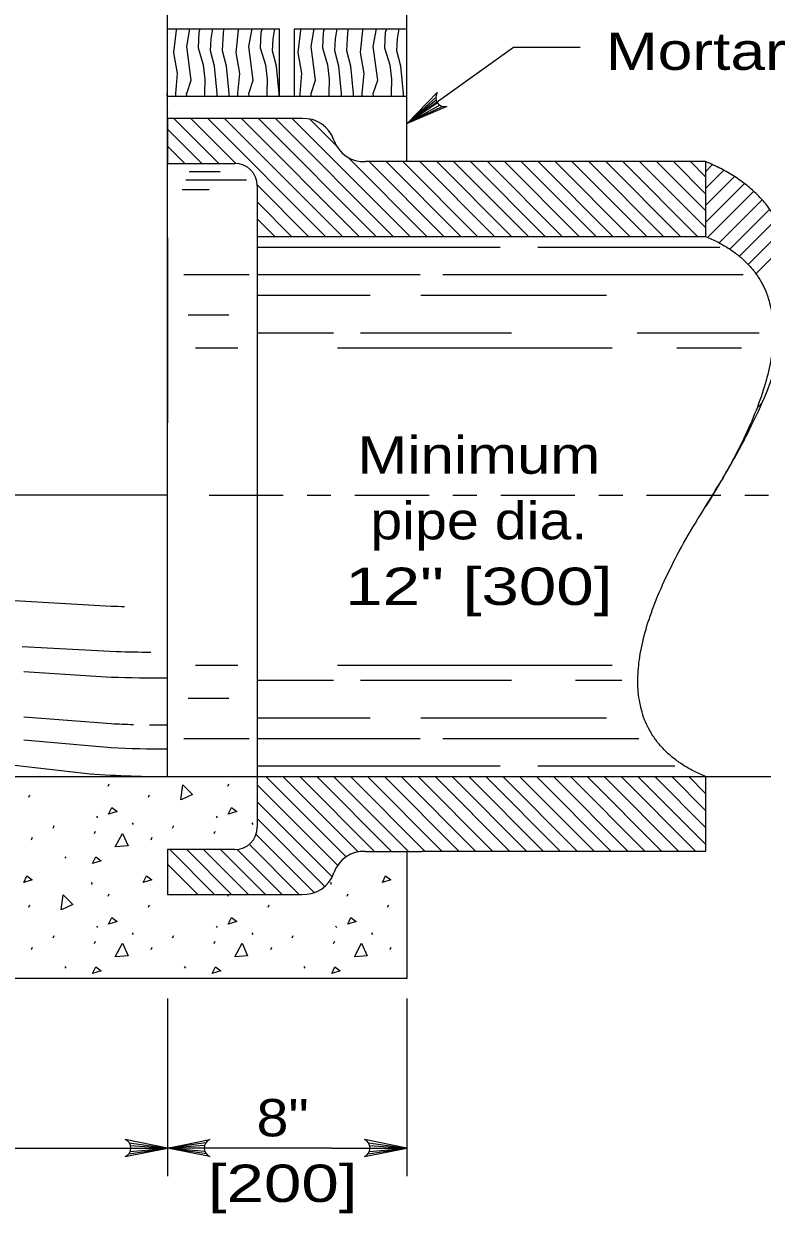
# Model space of a CAD drawing. Extents: x 1083.1 to 1117.1, y 719.4 to 763.4.
# Drawn here: x 1108.681 to 1111.769, y 727.812 to 732.781 of the extents above; entities that cross this region are included whole.
import ezdxf
from ezdxf.enums import TextEntityAlignment as Align

# ---------------------------------------------------------------- set-up
doc = ezdxf.new("R2010")
doc.units = 0
doc.header["$LTSCALE"] = 0.062
doc.linetypes.add('DOT_DASHED', pattern=[7.7, 5, -1.2, 0.3, -1.2])
doc.layers.add('1', color=7, linetype='Continuous', lineweight=13)

msp = doc.modelspace()

# ---------------------------------------------------------------- linework, layer by layer
at = {"layer": '1', "lineweight": 25}
for p, q in [((1109.28242, 729.63575), (1109.28242, 733.88517)), ((1109.84492, 732.38542), (1109.28242, 732.38542)), ((1109.28242, 732.198), (1109.56367, 732.198)), ((1111.53233, 732.20567), (1111.53233, 731.89317)), ((1109.65742, 731.89308), (1109.65742, 729.63575)), ((1108.64175, 729.68367), (1108.9355, 729.64958)), ((1110.1105, 729.32333), (1110.34492, 729.32333)), ((1110.28242, 729.32333), (1110.28242, 728.79217)), ((1111.53233, 729.32333), (1110.34492, 729.32333)), ((1110.28242, 728.79217), (1106.03258, 728.79217))]:
    msp.add_line(p, q, dxfattribs=at)
at = {"layer": '1'}
for p, q in [((1109.28242, 732.76033), (1109.75117, 732.76033)), ((1109.75117, 732.47908), (1109.75117, 732.76033)), ((1109.28017, 732.47908), (1109.28017, 732.48983)), ((1109.28242, 732.47908), (1110.28242, 732.47908)), ((1109.31683, 732.47908), (1109.31658, 732.48983)), ((1109.36308, 732.47908), (1109.36233, 732.49075)), ((1109.437, 732.48983), (1109.4375, 732.47908)), ((1109.4895, 732.47908), (1109.4895, 732.48983)), ((1109.54017, 732.47908), (1109.54017, 732.48983)), ((1109.57683, 732.47908), (1109.57658, 732.48983)), ((1109.62308, 732.47908), (1109.62233, 732.49075)), ((1109.697, 732.48983), (1109.6975, 732.47908)), ((1109.7495, 732.47908), (1109.7495, 732.48983)), ((1109.83683, 732.47908), (1109.83658, 732.48983)), ((1109.88308, 732.47908), (1109.88233, 732.49075)), ((1109.957, 732.48983), (1109.9575, 732.47908)), ((1110.0095, 732.47908), (1110.0095, 732.48983)), ((1110.06017, 732.47908), (1110.06017, 732.48983)), ((1110.09683, 732.47908), (1110.09658, 732.48983)), ((1110.14308, 732.47908), (1110.14233, 732.49075)), ((1110.217, 732.48983), (1110.2175, 732.47908)), ((1110.2695, 732.47908), (1110.2695, 732.48983)), ((1110.404, 732.474), (1110.285, 732.36425)), ((1110.40583, 732.46175), (1110.285, 732.36425)), ((1110.411, 732.4515), (1110.285, 732.36425)), ((1109.28242, 732.41658), (1109.28008, 732.41658)), ((1109.28117, 732.41658), (1109.28242, 732.41233)), ((1110.4215, 732.44125), (1110.285, 732.36425)), ((1110.43242, 732.43625), (1110.285, 732.36425)), ((1109.28242, 732.38542), (1109.28242, 732.198)), ((1109.4965, 732.198), (1109.309, 732.38542)), ((1109.56767, 732.19758), (1109.37975, 732.38542)), ((1109.94275, 731.89317), (1109.45042, 732.38542)), ((1110.0135, 731.89317), (1109.52117, 732.38542)), ((1110.08417, 731.89317), (1109.59183, 732.38542)), ((1110.15492, 731.89317), (1109.66258, 732.38542)), ((1110.22558, 731.89317), (1109.73325, 732.38542)), ((1110.29633, 731.89317), (1109.804, 732.38542)), ((1109.98942, 732.27075), (1109.87692, 732.38317)), ((1109.42583, 732.198), (1109.28242, 732.34142)), ((1109.35508, 732.198), (1109.28242, 732.27067)), ((1109.28442, 732.198), (1109.28242, 732.2)), ((1110.367, 731.89317), (1110.036, 732.22417)), ((1110.43775, 731.89317), (1110.12525, 732.20567)), ((1110.50842, 731.89317), (1110.19592, 732.20567)), ((1110.57917, 731.89317), (1110.26667, 732.20567)), ((1110.64983, 731.89317), (1110.33733, 732.20567)), ((1110.7205, 731.89317), (1110.40808, 732.20567)), ((1110.79117, 731.89317), (1110.47875, 732.20567)), ((1110.86192, 731.89317), (1110.5495, 732.20567)), ((1110.93267, 731.89317), (1110.62025, 732.20567)), ((1111.00333, 731.89317), (1110.69083, 732.20567)), ((1111.07408, 731.89317), (1110.76158, 732.20567)), ((1111.14475, 731.89317), (1110.83225, 732.20567)), ((1111.2155, 731.89317), (1110.903, 732.20567)), ((1111.28617, 731.89317), (1110.97367, 732.20567)), ((1111.35692, 731.89317), (1111.04442, 732.20567)), ((1111.42758, 731.89317), (1111.11508, 732.20567)), ((1111.49833, 731.89317), (1111.18583, 732.20567)), ((1111.53233, 731.92983), (1111.2565, 732.20567)), ((1111.53233, 732.00058), (1111.32725, 732.20567)), ((1111.53233, 732.07125), (1111.39792, 732.20567)), ((1111.53233, 732.142), (1111.46867, 732.20567)), ((1109.37342, 732.16392), (1109.50308, 732.16392)), ((1111.53233, 732.16325), (1111.56183, 732.19275)), ((1111.53233, 732.09258), (1111.609, 732.16925)), ((1109.28242, 732.13542), (1109.28008, 732.13542)), ((1109.35867, 732.129), (1109.61258, 732.129)), ((1109.87208, 731.89317), (1109.65717, 732.108)), ((1111.53233, 732.02183), (1111.65342, 732.14292)), ((1111.53233, 731.95117), (1111.695, 732.11383)), ((1109.34367, 732.08908), (1109.45575, 732.08908)), ((1111.54133, 731.88942), (1111.73358, 732.08167)), ((1111.589, 731.86642), (1111.76875, 732.04617)), ((1109.80133, 731.89317), (1109.65742, 732.03708)), ((1111.63333, 731.84), (1111.80042, 732.00708)), ((1109.73067, 731.89317), (1109.65742, 731.96642)), ((1111.674, 731.80992), (1111.82817, 731.96408)), ((1111.71058, 731.77592), (1111.85158, 731.91683)), ((1109.28242, 731.88658), (1109.28242, 731.1145)), ((1109.65742, 731.84867), (1110.67333, 731.84867)), ((1110.8305, 731.84867), (1111.59208, 731.84867)), ((1111.74258, 731.73725), (1111.8705, 731.865)), ((1109.28242, 731.73033), (1109.28008, 731.73033)), ((1109.35117, 731.73367), (1109.62408, 731.73367)), ((1109.65742, 731.73367), (1110.33842, 731.73367)), ((1110.43408, 731.73367), (1111.68992, 731.73367)), ((1109.65742, 731.64742), (1110.12992, 731.64742)), ((1110.34183, 731.64742), (1111.11758, 731.64742)), ((1109.36825, 731.56592), (1109.53867, 731.56592)), ((1109.28242, 731.14683), (1109.28242, 731.46583)), ((1109.65742, 731.49058), (1109.97617, 731.49058)), ((1110.08892, 731.49058), (1110.72108, 731.49058)), ((1111.24667, 731.49058), (1111.75592, 731.49058)), ((1109.28242, 731.44917), (1109.28008, 731.44917)), ((1109.399, 731.42692), (1109.57625, 731.42692)), ((1109.99325, 731.42692), (1111.1415, 731.42692)), ((1111.4115, 731.42692), (1111.68308, 731.42692)), ((1111.74742, 731.1765), (1111.76867, 731.19767)), ((1111.69367, 731.052), (1111.70417, 731.0625)), ((1109.28242, 731.04725), (1109.28008, 731.04725)), ((1111.61608, 730.90367), (1111.61858, 730.90617)), ((1109.28242, 730.85983), (1109.28008, 730.85983)), ((1108.28208, 730.39208), (1109.04675, 730.348)), ((1108.67475, 730.17933), (1109.06892, 730.15858)), ((1108.68117, 730.07492), (1109.04675, 730.052)), ((1109.399, 730.10208), (1109.57625, 730.10208)), ((1109.99325, 730.10208), (1111.1415, 730.10208)), ((1109.65742, 730.03842), (1109.97617, 730.03842)), ((1110.08892, 730.03842), (1110.72108, 730.03842)), ((1110.98767, 730.03842), (1111.18175, 730.03842)), ((1109.36825, 729.96308), (1109.53867, 729.96308)), ((1108.68117, 729.88608), (1109.04675, 729.85708)), ((1109.65742, 729.88158), (1110.12992, 729.88158)), ((1110.34183, 729.88158), (1111.11758, 729.88158)), ((1108.68117, 729.78925), (1109.04675, 729.75717)), ((1109.35117, 729.79533), (1109.62408, 729.79533)), ((1109.65742, 729.79533), (1110.33842, 729.79533)), ((1110.43408, 729.79533), (1111.25267, 729.79533)), ((1109.65742, 729.68025), (1110.67333, 729.68025)), ((1110.8305, 729.68025), (1111.40433, 729.68025)), ((1108.96517, 729.64942), (1108.96583, 729.64408)), ((1110.02925, 729.30067), (1109.69408, 729.63575)), ((1110.07958, 729.321), (1109.76475, 729.63575)), ((1110.148, 729.32333), (1109.8355, 729.63575)), ((1110.21867, 729.32333), (1109.90617, 729.63575)), ((1110.28942, 729.32333), (1109.97692, 729.63575)), ((1110.36008, 729.32333), (1110.04758, 729.63575)), ((1110.43083, 729.32333), (1110.11833, 729.63575)), ((1110.50158, 729.32333), (1110.18908, 729.63575)), ((1110.57225, 729.32333), (1110.25975, 729.63575)), ((1110.643, 729.32333), (1110.3305, 729.63575)), ((1110.71367, 729.32333), (1110.40117, 729.63575)), ((1110.78433, 729.32333), (1110.47192, 729.63575)), ((1110.855, 729.32333), (1110.54258, 729.63575)), ((1110.92575, 729.32333), (1110.61333, 729.63575)), ((1110.99642, 729.32333), (1110.684, 729.63575)), ((1111.06717, 729.32333), (1110.75467, 729.63575)), ((1111.13783, 729.32333), (1110.82533, 729.63575)), ((1111.20858, 729.32333), (1110.89608, 729.63575)), ((1111.27925, 729.32333), (1110.96675, 729.63575)), ((1111.35, 729.32333), (1111.0375, 729.63575)), ((1111.42067, 729.32333), (1111.10817, 729.63575)), ((1111.49142, 729.32333), (1111.17892, 729.63575)), ((1111.53233, 729.35308), (1111.24958, 729.63575)), ((1111.53233, 729.42383), (1111.32033, 729.63575)), ((1111.53233, 729.49458), (1111.39108, 729.63575)), ((1111.53233, 729.56525), (1111.46175, 729.63575)), ((1111.53233, 729.63575), (1112.9445, 729.63575)), ((1109.03392, 729.59525), (1109.03833, 729.60525)), ((1109.53392, 729.59525), (1109.53833, 729.60525)), ((1109.99367, 729.2655), (1109.65742, 729.60175)), ((1108.70267, 729.54967), (1108.70717, 729.55967)), ((1109.20258, 729.54967), (1109.20708, 729.55967)), ((1109.97083, 729.21767), (1109.65742, 729.53108)), ((1108.98517, 729.47092), (1108.98967, 729.46425)), ((1109.48517, 729.47092), (1109.48967, 729.46425)), ((1108.80375, 729.42092), (1108.80817, 729.43092)), ((1109.13475, 729.44267), (1109.13917, 729.436)), ((1109.30367, 729.42092), (1109.30808, 729.43092)), ((1109.63475, 729.44267), (1109.63917, 729.436)), ((1109.94067, 729.17717), (1109.65742, 729.46033)), ((1108.71383, 729.37225), (1108.71825, 729.38225)), ((1108.97683, 729.39775), (1108.98125, 729.40775)), ((1109.21375, 729.37225), (1109.21817, 729.38225)), ((1109.47683, 729.39775), (1109.48125, 729.40775)), ((1109.896, 729.15108), (1109.65242, 729.39467)), ((1109.47933, 729.1435), (1109.29183, 729.331)), ((1109.55, 729.1435), (1109.3625, 729.331)), ((1109.62075, 729.1435), (1109.43325, 729.331)), ((1109.69142, 729.1435), (1109.50392, 729.331)), ((1109.76217, 729.1435), (1109.57358, 729.332)), ((1109.83283, 729.1435), (1109.62333, 729.353)), ((1108.85258, 729.30117), (1108.857, 729.2945)), ((1109.40858, 729.1435), (1109.28242, 729.26967)), ((1108.96467, 729.19475), (1108.96583, 729.18475)), ((1109.96467, 729.19475), (1109.96583, 729.18475)), ((1109.03392, 729.13583), (1109.03833, 729.14583)), ((1109.53392, 729.13583), (1109.53733, 729.1435)), ((1110.03392, 729.13583), (1110.03833, 729.14583)), ((1108.70267, 729.09025), (1108.70717, 729.10025)), ((1109.20258, 729.09025), (1109.20708, 729.10025)), ((1109.70258, 729.09025), (1109.70708, 729.10025)), ((1110.20258, 729.09025), (1110.20708, 729.10025)), ((1108.80375, 728.96158), (1108.80817, 728.97158)), ((1108.98517, 729.01158), (1108.98967, 729.00492)), ((1109.13475, 728.98333), (1109.13917, 728.97667)), ((1109.30367, 728.96158), (1109.30808, 728.97158)), ((1109.48517, 729.01158), (1109.48967, 729.00492)), ((1109.63475, 728.98333), (1109.63917, 728.97667)), ((1109.80367, 728.96158), (1109.80808, 728.97158)), ((1109.98517, 729.01158), (1109.98967, 729.00492)), ((1110.13475, 728.98333), (1110.13917, 728.97667)), ((1108.71383, 728.91292), (1108.71825, 728.92292)), ((1108.97683, 728.93842), (1108.98125, 728.94842)), ((1109.21375, 728.91292), (1109.21817, 728.92292)), ((1109.47683, 728.93842), (1109.48125, 728.94842)), ((1109.71375, 728.91292), (1109.71817, 728.92292)), ((1109.97683, 728.93842), (1109.98125, 728.94842)), ((1110.21375, 728.91292), (1110.21817, 728.92292)), ((1108.85258, 728.84183), (1108.857, 728.83517)), ((1109.3525, 728.84183), (1109.35692, 728.83517)), ((1109.8525, 728.84183), (1109.85692, 728.83517)), ((1109.28242, 728.70883), (1109.28242, 727.96692)), ((1110.28242, 728.70883), (1110.28242, 727.96692)), ((1108.47742, 728.08383), (1109.28242, 728.08383)), ((1109.12025, 728.05908), (1109.28242, 728.08383)), ((1109.12217, 728.10633), (1109.28242, 728.08383)), ((1109.12642, 728.0695), (1109.28242, 728.08383)), ((1109.12758, 728.09517), (1109.28242, 728.08383)), ((1109.12925, 728.08383), (1109.28242, 728.08383)), ((1109.44275, 728.10633), (1109.28242, 728.08383)), ((1109.43733, 728.09517), (1109.28242, 728.08383)), ((1109.96825, 728.08383), (1109.28242, 728.08383)), ((1109.43567, 728.08383), (1109.28242, 728.08383)), ((1109.4385, 728.0695), (1109.28242, 728.08383)), ((1109.44467, 728.05908), (1109.28242, 728.08383)), ((1109.96825, 728.08383), (1110.28242, 728.08383)), ((1110.12017, 728.05908), (1110.28242, 728.08383)), ((1110.12208, 728.10633), (1110.28242, 728.08383)), ((1110.12633, 728.0695), (1110.28242, 728.08383)), ((1110.1275, 728.09517), (1110.28242, 728.08383)), ((1110.12917, 728.08383), (1110.28242, 728.08383))]:
    msp.add_line(p, q, dxfattribs=at)
at = {"layer": '1', "linetype": 'DOT_DASHED'}
msp.add_line((1109.45583, 730.81133), (1112.25767, 730.81133), dxfattribs=at)
at = {"layer": '1', "lineweight": 25}
for points in [[(1110.28242, 732.20567), (1110.28242, 733.23258), (1110.28242, 733.72892)], [(1111.53233, 732.20567), (1110.34492, 732.20567), (1110.1105, 732.20567)], [(1109.65742, 732.10425), (1109.65742, 731.89317), (1111.53233, 731.89317)], [(1109.28242, 730.81133), (1108.936, 730.81133), (1107.03175, 730.81133)], [(1106.03258, 729.63575), (1109.65742, 729.63575), (1109.65742, 729.42475)], [(1109.65742, 729.63575), (1111.53233, 729.63575), (1111.53233, 729.32333)], [(1109.56367, 729.331), (1109.28242, 729.331), (1109.28242, 729.1435), (1109.84492, 729.1435)]]:
    msp.add_lwpolyline(points, dxfattribs=at)
at = {"layer": '1'}
for points in [[(1109.31658, 732.49075), (1109.32458, 732.57308), (1109.30867, 732.66108), (1109.3195, 732.75433), (1109.32108, 732.76033)], [(1109.36242, 732.49075), (1109.38108, 732.54558), (1109.36267, 732.68692), (1109.37583, 732.76033)], [(1109.41767, 732.76033), (1109.41267, 732.74475), (1109.41033, 732.68108), (1109.43133, 732.60992), (1109.4385, 732.54958), (1109.437, 732.49075)], [(1109.4895, 732.49075), (1109.47842, 732.60458), (1109.46183, 732.669), (1109.46458, 732.71875), (1109.47125, 732.76033)], [(1109.54017, 732.49075), (1109.52908, 732.60458), (1109.5125, 732.669), (1109.51533, 732.71875), (1109.51792, 732.76033)], [(1109.57658, 732.49075), (1109.58458, 732.57308), (1109.56867, 732.66108), (1109.5795, 732.75433), (1109.58108, 732.76033)], [(1109.62242, 732.49075), (1109.64108, 732.54558), (1109.62267, 732.68692), (1109.63583, 732.76033)], [(1109.67767, 732.76033), (1109.67267, 732.74475), (1109.67033, 732.68108), (1109.69133, 732.60992), (1109.6985, 732.54958), (1109.697, 732.49075)], [(1109.7495, 732.49075), (1109.73842, 732.60458), (1109.72183, 732.669), (1109.72458, 732.71875), (1109.73125, 732.76033)], [(1109.81367, 732.47908), (1109.81367, 732.76033), (1110.28242, 732.76033)], [(1109.83658, 732.49075), (1109.84458, 732.57308), (1109.82867, 732.66108), (1109.8395, 732.75433), (1109.84108, 732.76033)], [(1109.88242, 732.49075), (1109.90108, 732.54558), (1109.88267, 732.68692), (1109.89583, 732.76033)], [(1109.93767, 732.76033), (1109.93267, 732.74475), (1109.93033, 732.68108), (1109.95133, 732.60992), (1109.9585, 732.54958), (1109.957, 732.49075)], [(1110.0095, 732.49075), (1109.99842, 732.60458), (1109.98183, 732.669), (1109.98458, 732.71875), (1109.99125, 732.76033)], [(1110.06017, 732.49075), (1110.04908, 732.60458), (1110.0325, 732.669), (1110.03533, 732.71875), (1110.03792, 732.76033)], [(1110.09658, 732.49075), (1110.10458, 732.57308), (1110.08867, 732.66108), (1110.0995, 732.75433), (1110.10108, 732.76033)], [(1110.14242, 732.49075), (1110.16108, 732.54558), (1110.14267, 732.68692), (1110.15583, 732.76033)], [(1110.19767, 732.76033), (1110.19267, 732.74475), (1110.19033, 732.68108), (1110.21133, 732.60992), (1110.2185, 732.54958), (1110.217, 732.49075)], [(1110.2695, 732.49075), (1110.25842, 732.60458), (1110.24183, 732.669), (1110.24458, 732.71875), (1110.25125, 732.76033)], [(1110.28242, 732.36492), (1110.72875, 732.68392), (1111.00842, 732.68392)], [(1110.45075, 732.43592), (1110.285, 732.36425), (1110.41042, 732.49417)], [(1109.33767, 729.53825), (1109.3465, 729.60167), (1109.38625, 729.56058), (1109.33867, 729.53858)], [(1109.06383, 729.34225), (1109.09383, 729.39883), (1109.11717, 729.34675), (1109.065, 729.34225)], [(1108.83775, 729.07883), (1108.84658, 729.14225), (1108.88633, 729.10117), (1108.83875, 729.07917)], [(1109.06383, 728.88292), (1109.09383, 728.9395), (1109.11717, 728.88742), (1109.065, 728.88292)], [(1109.56383, 728.88292), (1109.59383, 728.9395), (1109.61717, 728.88742), (1109.565, 728.88292)], [(1110.06383, 728.88292), (1110.09383, 728.9395), (1110.11717, 728.88742), (1110.065, 728.88292)], [(1109.10533, 728.04842), (1109.28242, 728.08383), (1109.10533, 728.11925)], [(1109.4595, 728.04842), (1109.28242, 728.08383), (1109.4595, 728.11925)], [(1110.10533, 728.04842), (1110.28242, 728.08383), (1110.10533, 728.11925)]]:
    msp.add_lwpolyline(points, dxfattribs=at)
for points in [[(1109.03608, 729.47867), (1109.04942, 729.50642), (1109.07167, 729.48975)], [(1109.53608, 729.47867), (1109.54942, 729.50642), (1109.57167, 729.48975)], [(1108.969, 729.27233), (1108.98233, 729.30008), (1109.00458, 729.28342)], [(1108.68075, 729.193), (1108.69408, 729.22075), (1108.71625, 729.20408)], [(1109.18067, 729.193), (1109.194, 729.22075), (1109.21617, 729.20408)], [(1110.18067, 729.193), (1110.194, 729.22075), (1110.21617, 729.20408)], [(1109.03608, 729.01933), (1109.04942, 729.04708), (1109.07167, 729.03042)], [(1109.53608, 729.01933), (1109.54942, 729.04708), (1109.57167, 729.03042)], [(1110.03608, 729.01933), (1110.04942, 729.04708), (1110.07167, 729.03042)], [(1108.969, 728.813), (1108.98233, 728.84075), (1109.00458, 728.82408)], [(1109.469, 728.813), (1109.48233, 728.84075), (1109.50458, 728.82408)], [(1109.969, 728.813), (1109.98233, 728.84075), (1110.00458, 728.82408)]]:
    msp.add_lwpolyline(points, close=True, dxfattribs=at)
for centre, start, end in [((1110.44231, 732.47323), 146.77712, 282.60325), ((1109.09107, 728.0839), 292.08605, 67.91218), ((1109.47382, 728.0839), 112.08782, 247.91395), ((1110.09102, 728.0839), 292.08605, 67.91218)]:
    msp.add_arc(centre, 0.03822, start, end, dxfattribs=at)
at = {"layer": '1', "lineweight": 25}
for centre, major_axis, ratio, start_param, end_param in [((1109.85244, 732.25364), (-0.13204, 0), 0.999895, 3.4645821, 4.7700699), ((1110.10287, 732.33746), (0.13204, 0), 0.999895, 3.4645821, 4.7700699), ((1109.56368, 732.10425), (0.09375, 0), 0.999895, 6.2831853, 7.8539816), ((1109.28244, 730.79195), (-2.24989, 0), 0.513872, 1.4159773, 1.5707963), ((1109.56368, 729.42474), (0.09375, 0), 0.999895, 4.712389, 6.2831853), ((1110.10287, 729.19153), (0.13204, 0), 0.999895, 1.5131154, 2.8186032), ((1109.85244, 729.27534), (-0.13204, 0), 0.999895, 1.5131154, 2.8186032)]:
    msp.add_ellipse(centre, major_axis=major_axis, ratio=ratio, start_param=start_param, end_param=end_param, dxfattribs=at)
at = {"layer": '1'}
for major_axis, ratio, start_param, end_param in [((2.24989, 0), 0.198424, 4.6074558, 4.6324215), ((-2.24989, 0), 0.282785, 1.4757459, 1.5398377), ((-2.24989, 0), 0.330706, 1.4658631, 1.5707963), ((-2.24989, 0), 0.417808, 1.4658631, 1.5071463), ((-2.24989, 0), 0.417808, 1.5370896, 1.5707963), ((-2.24989, 0), 0.46247, 1.4658631, 1.5707963)]:
    msp.add_ellipse((1109.28244, 730.79195), major_axis=major_axis, ratio=ratio, start_param=start_param, end_param=end_param, dxfattribs=at)
at = {"layer": '1', "lineweight": 25}
for points in [[(1111.53233, 730.7645), (1112.25583, 731.904), (1111.53233, 732.20567)], [(1111.53233, 731.89317), (1112.099, 731.657), (1111.53233, 730.7645)], [(1111.53233, 729.63583), (1110.96567, 729.87208), (1111.53233, 730.7645)]]:
    msp.add_open_spline(points, degree=2, dxfattribs=at)

# ---------------------------------------------------------------- texts
at = {"layer": '1', "width": 1.25}
msp.add_text('Mortar', height=0.156, dxfattribs=at).set_placement((1111.11475, 732.58883))
at = {"layer": '1'}
for s, width, p in [('Minimum', 1.2, (1110.58396, 730.90125)), ('pipe dia.', 1.15, (1110.58396, 730.62717)), ('12" [300]', 1.35, (1110.58392, 730.35308)), ('8"', 1.15, (1109.76375, 728.13275)), ('[200]', 1.35, (1109.76375, 727.85867))]:
    msp.add_text(s, height=0.156, dxfattribs=dict(at, width=width)).set_placement(p, align=Align.CENTER)

doc.saveas('drawing.dxf')
